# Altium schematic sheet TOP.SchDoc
size A3
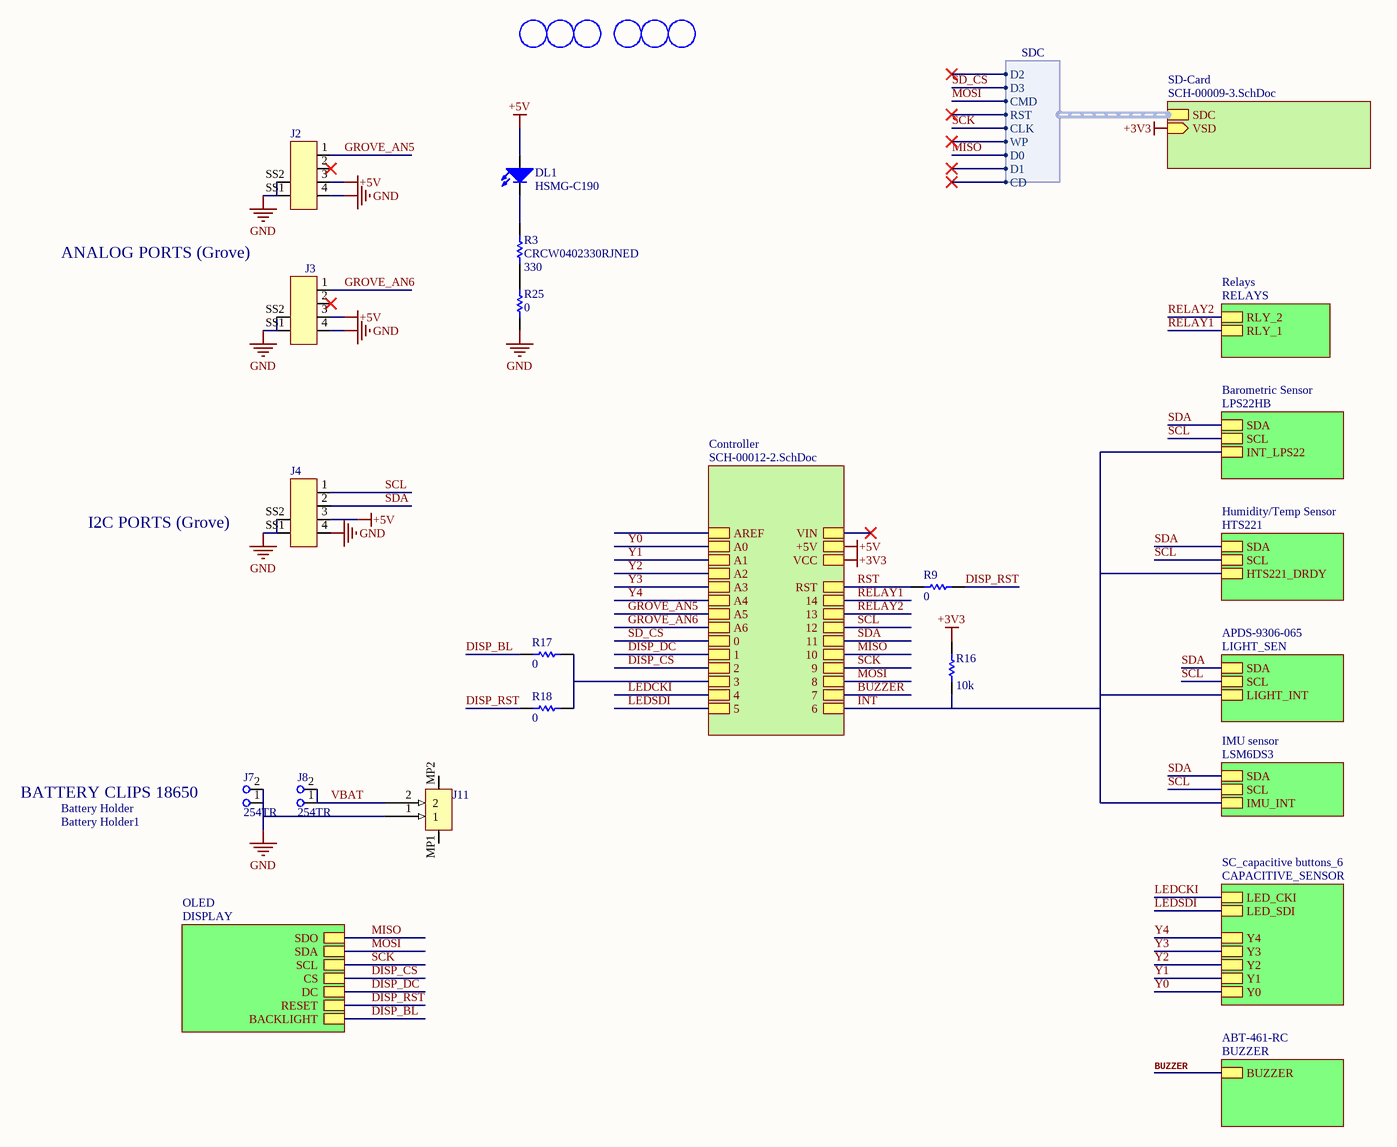
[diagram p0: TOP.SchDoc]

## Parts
Battery_Holder1  Battery Holder  [Battery Holder-Footprint-1]  (no BOM)
DL1  HSMG-C190  [LEDC1608X80N-AK]
FD1  Fiducial mark 1.5mm  [FIDUCIAL-1.5]  (value not drawn)  (no BOM)
FD2  Fiducial mark 1.5mm  [FIDUCIAL-1.5]  (value not drawn)  (no BOM)
FD3  Fiducial mark 1.5mm  [FIDUCIAL-1.5]  (value not drawn)  (no BOM)
FD4  Fiducial mark 1.5mm  [FIDUCIAL-1.5]  (value not drawn)  (no BOM)
FD5  Fiducial mark 1.5mm  [FIDUCIAL-1.5]  (value not drawn)  (no BOM)
FD6  Fiducial mark 1.5mm  [FIDUCIAL-1.5]  (value not drawn)  (no BOM)
J2  320110032  [320110032-Footprint-1]  (value not drawn)
J3  320110032  [320110032-Footprint-1]  (value not drawn)
J4  320110032  [320110032-Footprint-1]  (value not drawn)
J7  254TR  [254TR-Footprint-1]
J8  254TR  [254TR-Footprint-1]
J11  B2B-PH-SM4-TB(LF)(SN)  [New footprint 1]  (value not drawn)
R3  CRCW0402330RJNED  value 330  [RES-0402]
R9  value 0  [RES-0402]  (hidden comment: CRCW04020000Z0EDC)
R16  value 10k  [RES-0402]  (hidden comment: CRCW040210K0JNED)
R17  value 0  [RES-0402]  (hidden comment: CRCW04020000Z0EDC)
R18  value 0  [RES-0402]  (hidden comment: CRCW04020000Z0EDC)
R25  value 0  [RES-0402]  (hidden comment: CRCW04020000Z0EDC)

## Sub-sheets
ABT-461-RC = BUZZER: BUZZER
APDS-9306-065 = LIGHT_SEN: SCL, SDA, LIGHT_INT
Barometric Sensor = LPS22HB: INT_LPS22, SDA, SCL
Controller = SCH-00012-2.SchDoc: RST, 14, 13, 12, 11, 10, 9, 8, 7, 6, AREF, A0, A1, A2, A3, A4, A5, A6, 0, 1, 2, 3, 4, 5, VCC, +5V, VIN
Humidity/Temp Sensor = HTS221: HTS221_DRDY, SCL, SDA
IMU sensor = LSM6DS3: SDA, SCL, IMU_INT
OLED = DISPLAY: RESET, SCL, BACKLIGHT, SDA, SDO, DC, CS
Relays = RELAYS: RLY_2, RLY_1
SC_capacitive buttons_6 = CAPACITIVE_SENSOR: Y3, Y2, Y4, Y1, Y0, LED_CKI, LED_SDI
SD-Card = SCH-00009-3.SchDoc: SDC (harness SDC), VSD (in)

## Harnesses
SDC: CD, CLK, CMD, D0, D1, D2, D3, RST, WP

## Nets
+3V3: R16.2 ; sheet Controller/VCC, sheet SD-Card/VSD
+5V: DL1.A J2.3 J3.3 J4.3 ; sheet Controller/+5V
GND: J2.4 J2.SS1 J2.SS2 J3.4 J3.SS1 J3.SS2 J4.4 J4.SS1 J4.SS2 J7.1(-) J7.2(GND) J11.1 R25.1
BUZZER: sheet ABT-461-RC/BUZZER, sheet Controller/7
DISP_BL: R17.2 ; sheet OLED/BACKLIGHT
DISP_CS: sheet OLED/CS, sheet Controller/2
DISP_DC: sheet OLED/DC, sheet Controller/1
DISP_RST: R9.1 R18.2 ; sheet OLED/RESET
GROVE_AN5: J2.1 ; sheet Controller/A5
GROVE_AN6: J3.1 ; sheet Controller/A6
INT: R16.1 ; sheet Barometric Sensor/INT_LPS22, sheet Humidity/Temp Sensor/HTS221_DRDY, sheet IMU sensor/IMU_INT, sheet APDS-9306-065/LIGHT_INT, sheet Controller/6
LEDCKI: sheet SC_capacitive buttons_6/LED_CKI, sheet Controller/4
LEDSDI: sheet SC_capacitive buttons_6/LED_SDI, sheet Controller/5
MISO: sheet OLED/SDO, sheet Controller/10, sheet SD-Card/SDC.D0
MOSI: sheet OLED/SDA, sheet Controller/8, sheet SD-Card/SDC.CMD
RELAY1: sheet Relays/RLY_1, sheet Controller/14
RELAY2: sheet Relays/RLY_2, sheet Controller/13
RST: R9.2 ; sheet Controller/RST
SCK: sheet OLED/SCL, sheet Controller/9, sheet SD-Card/SDC.CLK
SCL: J4.1 ; sheet Barometric Sensor/SCL, sheet Humidity/Temp Sensor/SCL, sheet IMU sensor/SCL, sheet APDS-9306-065/SCL, sheet Controller/12
SD_CS: sheet Controller/0, sheet SD-Card/SDC.D3
SDA: J4.2 ; sheet Barometric Sensor/SDA, sheet Humidity/Temp Sensor/SDA, sheet IMU sensor/SDA, sheet APDS-9306-065/SDA, sheet Controller/11
VBAT: J8.1(-1) J8.2(GND) J11.2
Y0: sheet SC_capacitive buttons_6/Y0, sheet Controller/A0
Y1: sheet SC_capacitive buttons_6/Y1, sheet Controller/A1
Y2: sheet SC_capacitive buttons_6/Y2, sheet Controller/A2
Y3: sheet SC_capacitive buttons_6/Y3, sheet Controller/A3
Y4: sheet SC_capacitive buttons_6/Y4, sheet Controller/A4
NetDL1_C: DL1.C R3.2
NetR3_1: R3.1 R25.2
NetR17_1: R17.1 R18.1 ; sheet Controller/3

Not connected (* = marked no-connect by the designer): J2 2*; J3 2*; J11 MP1 MP2

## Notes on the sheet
- ANALOG PORTS (Grove)
- I2C PORTS (Grove)
- (near Battery_Holder1) BATTERY CLIPS 18650

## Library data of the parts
Battery_Holder1 = UT0019-A.1: Battery holder marker
DL1 = L0009-A.3: LED SMD 0603 GREEN/568 15mcd 120^; Manufacturer: Broadcom; Code Arduino: 2204
FD1-FD6 = UT0000-A.2
J2-J4 = J0114-A.4: CONN GROVE SMD-90D(4+2P-2.0) 320110032; Manufacturer: Seeed; Code Arduino: A5410
J7 J8 = J0053-A.3: CONN BATTERY HOLDER 18650 CLIP SMT; Manufacturer: Keystone Electronics; Code Arduino: J0053
J11 = J0103-A.2: CONN HEADER SMD 2 POS 0.079" (2.00mm); Manufacturer: JST; Code Arduino: J0103
R3 = R0017-A.3: RES CHIP 0402 330R 5% 1/16W; Manufacturer: Vishay; Power: 63mW; Code Arduino: 2229
R9 R17 R18 R25 = R0000-A.3: RES CHIP 0402 0R 1/16W; Manufacturer: Vishay; Code Arduino: 0039; Power: 63mW; Tolerance: J
R16 = R0004-A.3: RES CHIP 0402 10K 5% 1/16W; Manufacturer: Vishay; Code Arduino: 0136; Power: 63mW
